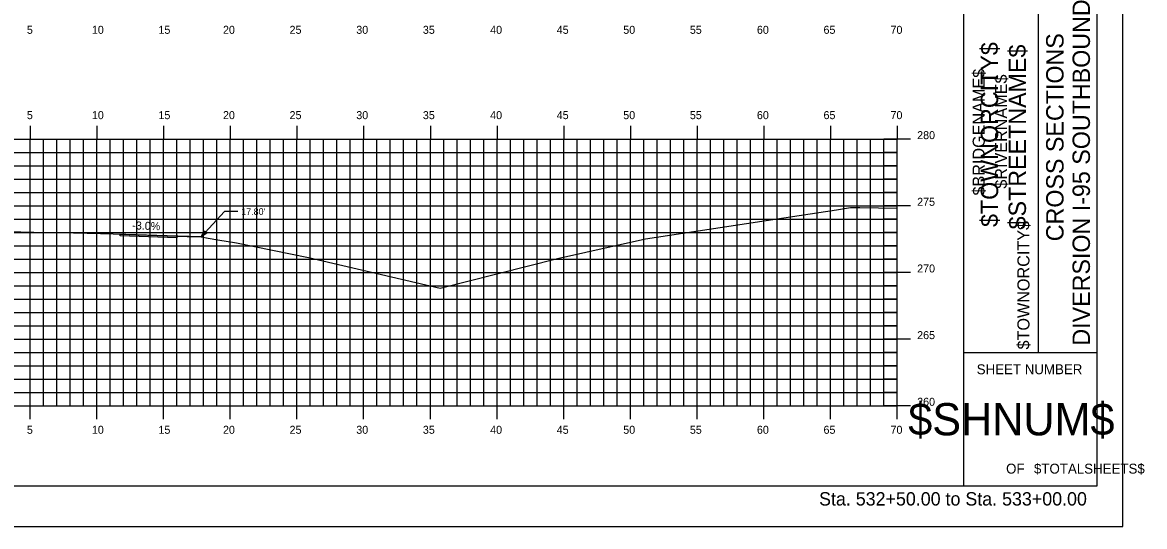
# Model space of a CAD drawing. Extents: x 1170543 to 1177585, y 609599 to 610623.
# Drawn here: x 1176692 to 1176776.2, y 609598.8 to 609636.6 of the extents above; entities that cross this region are included whole.
import ezdxf

# ---------------------------------------------------------------- set-up
doc = ezdxf.new("R2010")
doc.units = 0
for name, color, linetype in [('ANNOTATION', 7, 'Continuous'), ('BORDER', 7, 'Continuous'), ('BRIDGE_TITLE', 7, 'Continuous'), ('D_Roadway_Centerline', 7, 'Continuous'), ('D_Roadway_Edge_TW', 7, 'Continuous'), ('H_V ANNOTATION', 7, 'Continuous'), ('HIGHWAY_TITLE', 7, 'Continuous'), ('MAJOR', 7, 'Continuous'), ('MINOR', 7, 'Continuous'), ('PLOT BOUNDARY', 7, 'Continuous'), ('S_Roadway_Centerline', 7, 'Continuous')]:
    doc.layers.add(name, color=color, linetype=linetype)

msp = doc.modelspace()

# ---------------------------------------------------------------- linework, layer by layer
at = {"layer": 'ANNOTATION'}
for p in [(1176705.417, 609620.546), (1176708.182, 609622.439)]:
    msp.add_line(p, (1176707.182, 609622.439), dxfattribs=at)
msp.add_lwpolyline([(1176705.849, 609620.827), (1176705.417, 609620.546), (1176705.666, 609620.997)], close=True, dxfattribs=at)
at = {"layer": 'BORDER'}
for p, q in [((1176762.609, 609601.875), (1176762.609, 609706.875)), ((1176772.609, 609601.875), (1176772.609, 609706.875)), ((1176768.2, 609611.875), (1176768.2, 609646.875)), ((1176762.609, 609611.875), (1176772.609, 609611.875)), ((1176612.609, 609601.872), (1176772.609, 609601.872))]:
    msp.add_line(p, q, dxfattribs=at)
at = {"layer": 'D_Roadway_Centerline'}
msp.add_lwpolyline([(1176699.346, 609620.748), (1176700.706, 609620.703), (1176703.609, 609620.607), (1176704.371, 609620.581), (1176705.417, 609620.546)], dxfattribs=at)
at = {"layer": 'D_Roadway_Edge_TW'}
msp.add_lwpolyline([(1176699.346, 609620.748), (1176705.417, 609620.546), (1176703.609, 609620.607), (1176703.609, 609620.482), (1176699.346, 609620.623), (1176699.346, 609620.748)], dxfattribs=at)
at = {"layer": 'MAJOR'}
for p, q in [((1176692.609, 609628.874), (1176692.609, 609627.872)), ((1176697.609, 609628.874), (1176697.609, 609627.872)), ((1176702.609, 609628.874), (1176702.609, 609627.872)), ((1176707.609, 609628.874), (1176707.609, 609627.872)), ((1176712.609, 609628.874), (1176712.609, 609627.872)), ((1176717.609, 609628.874), (1176717.609, 609627.872)), ((1176722.609, 609628.874), (1176722.609, 609627.872)), ((1176727.609, 609628.874), (1176727.609, 609627.872)), ((1176732.609, 609628.874), (1176732.609, 609627.872)), ((1176737.609, 609628.874), (1176737.609, 609627.872)), ((1176742.609, 609628.874), (1176742.609, 609627.872)), ((1176747.609, 609628.874), (1176747.609, 609627.872)), ((1176752.609, 609628.874), (1176752.609, 609627.872)), ((1176757.609, 609628.874), (1176757.609, 609627.872)), ((1176617.609, 609627.872), (1176757.609, 609627.872)), ((1176617.609, 609627.872), (1176757.609, 609627.872)), ((1176692.609, 609607.872), (1176692.609, 609627.872)), ((1176697.609, 609607.872), (1176697.609, 609627.872)), ((1176702.609, 609607.872), (1176702.609, 609627.872)), ((1176707.609, 609607.872), (1176707.609, 609627.872)), ((1176712.609, 609607.872), (1176712.609, 609627.872)), ((1176717.609, 609607.872), (1176717.609, 609627.872)), ((1176722.609, 609607.872), (1176722.609, 609627.872)), ((1176727.609, 609607.872), (1176727.609, 609627.872)), ((1176732.609, 609607.872), (1176732.609, 609627.872)), ((1176737.609, 609607.872), (1176737.609, 609627.872)), ((1176742.609, 609607.872), (1176742.609, 609627.872)), ((1176747.609, 609607.872), (1176747.609, 609627.872)), ((1176752.609, 609607.872), (1176752.609, 609627.872)), ((1176758.611, 609627.872), (1176756.607, 609627.872)), ((1176757.609, 609607.872), (1176757.609, 609627.872)), ((1176757.609, 609607.872), (1176757.609, 609627.872)), ((1176617.609, 609622.872), (1176757.609, 609622.872)), ((1176758.611, 609622.872), (1176756.607, 609622.872)), ((1176617.609, 609617.872), (1176757.609, 609617.872)), ((1176758.611, 609617.872), (1176756.607, 609617.872)), ((1176617.609, 609612.872), (1176757.609, 609612.872)), ((1176758.611, 609612.872), (1176756.607, 609612.872)), ((1176617.609, 609607.872), (1176757.609, 609607.872)), ((1176617.609, 609607.872), (1176757.609, 609607.872)), ((1176692.609, 609606.87), (1176692.609, 609607.872)), ((1176697.609, 609606.87), (1176697.609, 609607.872)), ((1176702.609, 609606.87), (1176702.609, 609607.872)), ((1176707.609, 609606.87), (1176707.609, 609607.872)), ((1176712.609, 609606.87), (1176712.609, 609607.872)), ((1176717.609, 609606.87), (1176717.609, 609607.872)), ((1176722.609, 609606.87), (1176722.609, 609607.872)), ((1176727.609, 609606.87), (1176727.609, 609607.872)), ((1176732.609, 609606.87), (1176732.609, 609607.872)), ((1176737.609, 609606.87), (1176737.609, 609607.872)), ((1176742.609, 609606.87), (1176742.609, 609607.872)), ((1176747.609, 609606.87), (1176747.609, 609607.872)), ((1176752.609, 609606.87), (1176752.609, 609607.872)), ((1176758.611, 609607.872), (1176756.607, 609607.872)), ((1176757.609, 609606.87), (1176757.609, 609607.872))]:
    msp.add_line(p, q, dxfattribs=at)
at = {"layer": 'MINOR'}
for p, q in [((1176693.609, 609607.872), (1176693.609, 609627.872)), ((1176694.609, 609607.872), (1176694.609, 609627.872)), ((1176695.609, 609607.872), (1176695.609, 609627.872)), ((1176696.609, 609607.872), (1176696.609, 609627.872)), ((1176698.609, 609607.872), (1176698.609, 609627.872)), ((1176699.609, 609607.872), (1176699.609, 609627.872)), ((1176700.609, 609607.872), (1176700.609, 609627.872)), ((1176701.609, 609607.872), (1176701.609, 609627.872)), ((1176703.609, 609607.872), (1176703.609, 609627.872)), ((1176704.609, 609607.872), (1176704.609, 609627.872)), ((1176705.609, 609607.872), (1176705.609, 609627.872)), ((1176706.609, 609607.872), (1176706.609, 609627.872)), ((1176708.609, 609607.872), (1176708.609, 609627.872)), ((1176709.609, 609607.872), (1176709.609, 609627.872)), ((1176710.609, 609607.872), (1176710.609, 609627.872)), ((1176711.609, 609607.872), (1176711.609, 609627.872)), ((1176713.609, 609607.872), (1176713.609, 609627.872)), ((1176714.609, 609607.872), (1176714.609, 609627.872)), ((1176715.609, 609607.872), (1176715.609, 609627.872)), ((1176716.609, 609607.872), (1176716.609, 609627.872)), ((1176718.609, 609607.872), (1176718.609, 609627.872)), ((1176719.609, 609607.872), (1176719.609, 609627.872)), ((1176720.609, 609607.872), (1176720.609, 609627.872)), ((1176721.609, 609607.872), (1176721.609, 609627.872)), ((1176723.609, 609607.872), (1176723.609, 609627.872)), ((1176724.609, 609607.872), (1176724.609, 609627.872)), ((1176725.609, 609607.872), (1176725.609, 609627.872)), ((1176726.609, 609607.872), (1176726.609, 609627.872)), ((1176728.609, 609607.872), (1176728.609, 609627.872)), ((1176729.609, 609607.872), (1176729.609, 609627.872)), ((1176730.609, 609607.872), (1176730.609, 609627.872)), ((1176731.609, 609607.872), (1176731.609, 609627.872)), ((1176733.609, 609607.872), (1176733.609, 609627.872)), ((1176734.609, 609607.872), (1176734.609, 609627.872)), ((1176735.609, 609607.872), (1176735.609, 609627.872)), ((1176736.609, 609607.872), (1176736.609, 609627.872)), ((1176738.609, 609607.872), (1176738.609, 609627.872)), ((1176739.609, 609607.872), (1176739.609, 609627.872)), ((1176740.609, 609607.872), (1176740.609, 609627.872)), ((1176741.609, 609607.872), (1176741.609, 609627.872)), ((1176743.609, 609607.872), (1176743.609, 609627.872)), ((1176744.609, 609607.872), (1176744.609, 609627.872)), ((1176745.609, 609607.872), (1176745.609, 609627.872)), ((1176746.609, 609607.872), (1176746.609, 609627.872)), ((1176748.609, 609607.872), (1176748.609, 609627.872)), ((1176749.609, 609607.872), (1176749.609, 609627.872)), ((1176750.609, 609607.872), (1176750.609, 609627.872)), ((1176751.609, 609607.872), (1176751.609, 609627.872)), ((1176753.609, 609607.872), (1176753.609, 609627.872)), ((1176754.609, 609607.872), (1176754.609, 609627.872)), ((1176755.609, 609607.872), (1176755.609, 609627.872)), ((1176756.609, 609607.872), (1176756.609, 609627.872)), ((1176617.609, 609626.872), (1176757.609, 609626.872)), ((1176757.609, 609626.872), (1176756.607, 609626.872)), ((1176617.609, 609625.872), (1176757.609, 609625.872)), ((1176757.609, 609625.872), (1176756.607, 609625.872)), ((1176617.609, 609624.872), (1176757.609, 609624.872)), ((1176757.609, 609624.872), (1176756.607, 609624.872)), ((1176617.609, 609623.872), (1176757.609, 609623.872)), ((1176757.609, 609623.872), (1176756.607, 609623.872)), ((1176617.609, 609621.872), (1176757.609, 609621.872)), ((1176757.609, 609621.872), (1176756.607, 609621.872)), ((1176617.609, 609620.872), (1176757.609, 609620.872)), ((1176757.609, 609620.872), (1176756.607, 609620.872)), ((1176617.609, 609619.872), (1176757.609, 609619.872)), ((1176757.609, 609619.872), (1176756.607, 609619.872)), ((1176617.609, 609618.872), (1176757.609, 609618.872)), ((1176757.609, 609618.872), (1176756.607, 609618.872)), ((1176617.609, 609616.872), (1176757.609, 609616.872)), ((1176757.609, 609616.872), (1176756.607, 609616.872)), ((1176617.609, 609615.872), (1176757.609, 609615.872)), ((1176757.609, 609615.872), (1176756.607, 609615.872)), ((1176617.609, 609614.872), (1176757.609, 609614.872)), ((1176757.609, 609614.872), (1176756.607, 609614.872)), ((1176617.609, 609613.872), (1176757.609, 609613.872)), ((1176757.609, 609613.872), (1176756.607, 609613.872)), ((1176617.609, 609611.872), (1176757.609, 609611.872)), ((1176757.609, 609611.872), (1176756.607, 609611.872)), ((1176617.609, 609610.872), (1176757.609, 609610.872)), ((1176757.609, 609610.872), (1176756.607, 609610.872)), ((1176617.609, 609609.872), (1176757.609, 609609.872)), ((1176757.609, 609609.872), (1176756.607, 609609.872)), ((1176617.609, 609608.872), (1176757.609, 609608.872)), ((1176757.609, 609608.872), (1176756.607, 609608.872))]:
    msp.add_line(p, q, dxfattribs=at)
at = {"layer": 'PLOT BOUNDARY'}
msp.add_lwpolyline([(1176604.516, 609598.813), (1176774.516, 609598.813), (1176774.516, 609708.813), (1176604.516, 609708.813)], close=True, dxfattribs=at)
at = {"layer": 'S_Roadway_Centerline'}
msp.add_lwpolyline([(1176689.917, 609620.966), (1176692.871, 609620.907), (1176694.85, 609620.862), (1176697.871, 609620.793), (1176699.784, 609620.735), (1176702.872, 609620.64), (1176703.685, 609620.61), (1176705.417, 609620.546), (1176705.963, 609620.456), (1176706.682, 609620.325), (1176708.077, 609620.099), (1176713.468, 609619.005), (1176723.356, 609616.694), (1176732.138, 609618.929), (1176738.735, 609620.395), (1176753.059, 609622.57), (1176754.105, 609622.746), (1176754.804, 609622.741), (1176757.609, 609622.69)], dxfattribs=at)

# ---------------------------------------------------------------- texts
at = {"layer": 'ANNOTATION'}
msp.add_text("17.80'", height=0.5, dxfattribs=at).set_placement((1176708.432, 609622.189))
msp.add_text('-3.0%', height=0.6, rotation=358.09711, dxfattribs=at).set_placement((1176700.256, 609621.109))
at = {"layer": 'BORDER'}
for s, height, rotation, p in [('DIVERSION I-95 SOUTHBOUND', 1.30428, 90, (1176772.063, 609612.385)), ('CROSS SECTIONS', 1.30428, 90, (1176770.085, 609620.214)), ('SHEET NUMBER', 0.74527, 360, (1176763.575, 609610.239)), ('$SHNUM$', 2.4194, 360, (1176758.442, 609605.655)), ('OF', 0.7453, 360, (1176765.776, 609602.785)), ('$TOTALSHEETS$', 0.74527, 360, (1176767.866, 609602.785))]:
    msp.add_text(s, height=height, rotation=rotation, dxfattribs=at).set_placement(p)
at = {"layer": 'BRIDGE_TITLE'}
for s, p in [('$BRIDGENAME$', (1176764.175, 609623.643)), ('$RIVERNAME$', (1176765.852, 609624.158)), ('$TOWNORCITY$', (1176767.529, 609612.096))]:
    msp.add_text(s, height=0.90716, rotation=90, dxfattribs=at).set_placement(p)
at = {"layer": 'H_V ANNOTATION'}
for s, height, p in [('5', 0.6, (1176692.36, 609635.772)), ('10', 0.6, (1176697.234, 609635.772)), ('15', 0.6, (1176702.226, 609635.772)), ('20', 0.6, (1176707.063, 609635.772)), ('25', 0.6, (1176712.055, 609635.772)), ('30', 0.6, (1176717.058, 609635.772)), ('35', 0.6, (1176722.05, 609635.772)), ('40', 0.6, (1176727.095, 609635.772)), ('45', 0.6, (1176732.087, 609635.772)), ('50', 0.6, (1176737.074, 609635.772)), ('55', 0.6, (1176742.066, 609635.772)), ('60', 0.6, (1176747.095, 609635.772)), ('65', 0.6, (1176752.087, 609635.772)), ('70', 0.6, (1176757.111, 609635.772)), ('5', 0.6, (1176692.36, 609629.372)), ('10', 0.6, (1176697.234, 609629.372)), ('15', 0.6, (1176702.226, 609629.372)), ('20', 0.6, (1176707.063, 609629.372)), ('25', 0.6, (1176712.055, 609629.372)), ('30', 0.6, (1176717.058, 609629.372)), ('35', 0.6, (1176722.05, 609629.372)), ('40', 0.6, (1176727.095, 609629.372)), ('45', 0.6, (1176732.087, 609629.372)), ('50', 0.6, (1176737.074, 609629.372)), ('55', 0.6, (1176742.066, 609629.372)), ('60', 0.6, (1176747.095, 609629.372)), ('65', 0.6, (1176752.087, 609629.372)), ('70', 0.6, (1176757.111, 609629.372)), ('280', 0.6, (1176759.109, 609627.872)), ('275', 0.6, (1176759.109, 609622.872)), ('270', 0.6, (1176759.109, 609617.872)), ('265', 0.6, (1176759.109, 609612.872)), ('260', 0.6, (1176759.109, 609607.872)), ('5', 0.6, (1176692.36, 609605.772)), ('10', 0.6, (1176697.234, 609605.772)), ('15', 0.6, (1176702.226, 609605.772)), ('20', 0.6, (1176707.063, 609605.772)), ('25', 0.6, (1176712.055, 609605.772)), ('30', 0.6, (1176717.058, 609605.772)), ('35', 0.6, (1176722.05, 609605.772)), ('40', 0.6, (1176727.095, 609605.772)), ('45', 0.6, (1176732.087, 609605.772)), ('50', 0.6, (1176737.074, 609605.772)), ('55', 0.6, (1176742.066, 609605.772)), ('60', 0.6, (1176747.095, 609605.772)), ('65', 0.6, (1176752.087, 609605.772)), ('70', 0.6, (1176757.111, 609605.772)), ('Sta. 532+50.00 to Sta. 533+00.00', 1.0002, (1176751.755, 609600.392))]:
    msp.add_text(s, height=height, dxfattribs=at).set_placement(p)
at = {"layer": 'HIGHWAY_TITLE'}
for s, p in [('$TOWNORCITY$', (1176765.181, 609621.284)), ('$STREETNAME$', (1176767.268, 609621.104))]:
    msp.add_text(s, height=1.30428, rotation=90, dxfattribs=at).set_placement(p)

doc.saveas('drawing.dxf')
